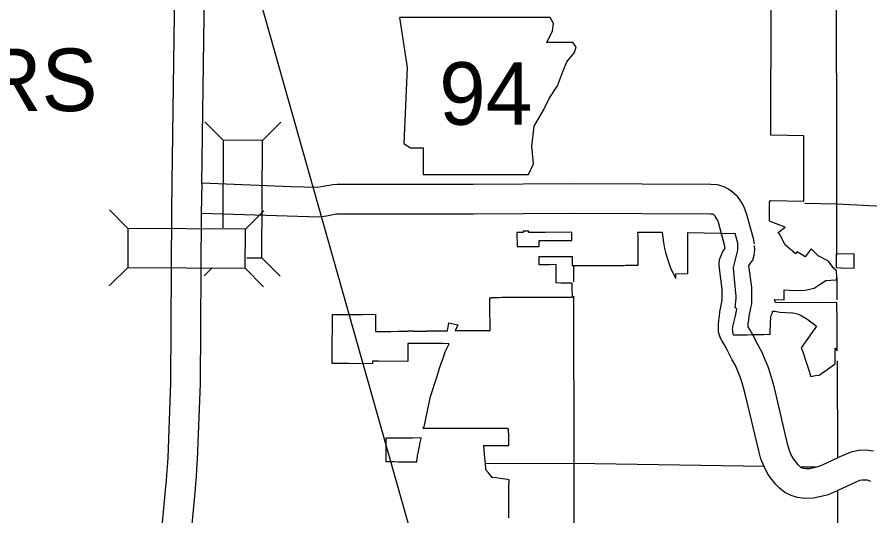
# Model space of a CAD drawing. Extents: x 309389.3 to 309420.2, y 336441.4 to 336461.2.
# Drawn here: x 309392.47 to 309393.778, y 336456.121 to 336456.886 of the extents above; entities that cross this region are included whole.
import ezdxf

# ---------------------------------------------------------------- set-up
doc = ezdxf.new("R2010")
doc.units = 0
for name, color, linetype in [('Level 24', 7, 'Continuous'), ('Level 37', 7, 'Continuous'), ('Level 4', 7, 'Continuous'), ('Level 62', 7, 'Continuous'), ('Level 63', 7, 'Continuous'), ('R_Axis Annot', 7, 'Continuous'), ('R_Contours', 7, 'Continuous')]:
    doc.layers.add(name, color=color, linetype=linetype)

msp = doc.modelspace()

# ---------------------------------------------------------------- linework, layer by layer
at = {"layer": 'Level 24'}
for points in [[(309392.8902, 336456.6257), (309392.7535, 336456.6309), (309392.7527, 336456.5848)], [(309393.6007, 336456.5379), (309393.5994, 336456.5464), (309393.5887, 336456.5845), (309393.5857, 336456.593), (309393.5825, 336456.5993), (309393.5789, 336456.6051), (309393.5747, 336456.6107), (309393.5673, 336456.6173), (309393.5608, 336456.6217), (309393.5544, 336456.6255), (309393.5439, 336456.6287), (309393.534, 336456.6289), (309393.3234, 336456.6302), (309393.1696, 336456.6292), (309392.9609, 336456.629), (309392.9541, 336456.6285), (309392.9489, 336456.6275), (309392.9444, 336456.6268), (309392.9364, 336456.6253), (309392.9308, 336456.6243), (309392.8902, 336456.6257)], [(309393.5558, 336456.531), (309393.5549, 336456.5367), (309393.5454, 336456.5706), (309393.5439, 336456.5749), (309393.5428, 336456.577), (309393.5412, 336456.5796), (309393.5411, 336456.5798), (309393.5394, 336456.5813), (309393.5364, 336456.5833), (309393.5363, 336456.5834), (309393.5335, 336456.5834), (309393.3234, 336456.5848), (309393.1698, 336456.5837), (309392.9626, 336456.5836), (309392.96, 336456.5834), (309392.957, 336456.5828), (309392.9522, 336456.582), (309392.9444, 336456.5806), (309392.934, 336456.5788), (309392.7527, 336456.5848)], [(309393.7832, 336456.22), (309393.7713, 336456.2213), (309393.7604, 336456.221), (309393.7488, 336456.2184), (309393.7371, 336456.214), (309393.7048, 336456.1987), (309393.6993, 336456.1965), (309393.692, 336456.1946), (309393.6854, 336456.193), (309393.6796, 336456.1929), (309393.6765, 336456.1933), (309393.674, 336456.1941), (309393.6719, 336456.1951), (309393.6697, 336456.197), (309393.6678, 336456.1988), (309393.6642, 336456.2035), (309393.66, 336456.2091), (309393.6567, 336456.2154), (309393.6538, 336456.2225), (309393.6521, 336456.2291), (309393.6313, 336456.3169), (309393.6284, 336456.328), (309393.6252, 336456.3383), (309393.6216, 336456.3495), (309393.6172, 336456.3601), (309393.6126, 336456.3711), (309393.6068, 336456.3817), (309393.5986, 336456.3976), (309393.5934, 336456.4065), (309393.5911, 336456.4109), (309393.591, 336456.4129), (309393.5912, 336456.4156), (309393.592, 336456.4205), (309393.5928, 336456.4269), (309393.5951, 336456.4401), (309393.5965, 336456.446), (309393.5969, 336456.4562), (309393.5965, 336456.4629), (309393.5965, 336456.4718), (309393.5923, 336456.5041), (309393.5923, 336456.5044), (309393.5923, 336456.5044), (309393.5938, 336456.5068), (309393.5981, 336456.513), (309393.6002, 336456.5209), (309393.6012, 336456.5289), (309393.6009, 336456.5353)], [(309393.7791, 336456.1736), (309393.7767, 336456.1744), (309393.7738, 336456.1753), (309393.7695, 336456.1757), (309393.766, 336456.1757), (309393.7618, 336456.1747), (309393.7549, 336456.1721), (309393.7229, 336456.157), (309393.7135, 336456.1532), (309393.703, 336456.1505), (309393.6912, 336456.1477), (309393.6773, 336456.1474), (309393.6668, 336456.1487), (309393.6569, 336456.1518), (309393.6471, 336456.1567), (309393.6393, 336456.163), (309393.6335, 336456.1687), (309393.628, 336456.1761), (309393.6215, 336456.1846), (309393.6154, 336456.1962), (309393.6106, 336456.2082), (309393.608, 336456.2182), (309393.5871, 336456.306), (309393.5847, 336456.3155), (309393.5818, 336456.3246), (309393.5789, 336456.334), (309393.5753, 336456.3426), (309393.5716, 336456.3513), (309393.5667, 336456.3603), (309393.5588, 336456.3756), (309393.5536, 336456.3845), (309393.5508, 336456.3899), (309393.5487, 336456.3935), (309393.5457, 336456.4023), (309393.5457, 336456.4089), (309393.5454, 336456.4138), (309393.5461, 336456.4211), (309393.547, 336456.4271), (309393.5479, 336456.4338), (309393.5506, 336456.4492), (309393.5513, 336456.4521), (309393.5514, 336456.4558), (309393.5511, 336456.4615), (309393.5511, 336456.4687), (309393.547, 336456.5001), (309393.5467, 336456.5058), (309393.5471, 336456.5138), (309393.5496, 336456.5202), (309393.5523, 336456.5262), (309393.5556, 336456.5314), (309393.5555, 336456.5335)]]:
    msp.add_lwpolyline(points, dxfattribs=at)
at = {"layer": 'Level 37'}
for p, q in [((309392.7864, 336456.697), (309392.7582, 336456.7254)), ((309392.8464, 336456.6966), (309392.8748, 336456.7247)), ((309392.7864, 336456.697), (309392.7856, 336456.5624)), ((309392.8464, 336456.6966), (309392.7864, 336456.697)), ((309392.8454, 336456.5166), (309392.8464, 336456.6966)), ((309392.6403, 336456.5617), (309392.6122, 336456.5902)), ((309392.8203, 336456.5607), (309392.8487, 336456.5889)), ((309392.8223, 336456.5168), (309392.8454, 336456.5166)), ((309392.8454, 336456.5166), (309392.8735, 336456.4882)), ((309392.64, 336456.5017), (309392.6115, 336456.4736)), ((309392.7692, 336456.501), (309392.7569, 336456.4888)), ((309392.82, 336456.5007), (309392.8481, 336456.4723))]:
    msp.add_line(p, q, dxfattribs=at)
msp.add_lwpolyline([(309392.64, 336456.5017), (309392.82, 336456.5007), (309392.8203, 336456.5607), (309392.6403, 336456.5617)], close=True, dxfattribs=at)
at = {"layer": 'Level 4'}
for points in [[(309393.7272, 336456.5204), (309393.7268, 336456.5996), (309393.7263, 336457.0003), (309393.7258, 336457.2014)], [(309393.6778, 336456.6003), (309393.7269, 336456.5994), (309394.129, 336456.579), (309394.5268, 336456.5747), (309394.8545, 336456.5709)], [(309393.3235, 336456.5053), (309393.3235, 336456.4797)], [(309393.7275, 336456.4523), (309393.7273, 336456.4858)], [(309393.3235, 336456.4578), (309393.3236, 336456.201), (309393.3228, 336455.7953), (309393.322, 336455.3953)], [(309393.7288, 336456.2097), (309393.728, 336456.3583)], [(309393.6155, 336456.1964), (309393.3236, 336456.2011), (309393.1883, 336456.2007)], [(309393.6938, 336456.1952), (309393.672, 336456.1955)], [(309393.7274, 336455.9452), (309393.7287, 336456.1596)]]:
    msp.add_lwpolyline(points, dxfattribs=at)
at = {"layer": 'Level 62'}
for points in [[(309393.6259, 336456.7821), (309393.6259, 336456.7825), (309393.626, 336456.8049), (309393.6261, 336456.8049), (309393.6261, 336456.8065), (309393.6262, 336456.8065), (309393.6263, 336456.8559), (309393.6263, 336456.8737), (309393.6263, 336456.9065)], [(309393.5707, 336456.4728), (309393.572, 336456.4578), (309393.5721, 336456.4549), (309393.5708, 336456.441), (309393.573, 336456.439), (309393.5728, 336456.439), (309393.5732, 336456.4378), (309393.571, 336456.4274), (309393.5675, 336456.4135), (309393.5672, 336456.4114), (309393.567, 336456.4099), (309393.567, 336456.4096), (309393.5669, 336456.4093), (309393.5668, 336456.4071), (309393.5669, 336456.405), (309393.5671, 336456.4029), (309393.5674, 336456.4007), (309393.5679, 336456.3983), (309393.5699, 336456.3983), (309393.5898, 336456.3985), (309393.5982, 336456.3987), (309393.6041, 336456.3988), (309393.6065, 336456.3989), (309393.6076, 336456.3989), (309393.6149, 336456.399), (309393.6232, 336456.3992), (309393.6245, 336456.3991), (309393.6246, 336456.3999), (309393.6247, 336456.4029), (309393.6254, 336456.4146), (309393.6261, 336456.427), (309393.6284, 336456.432), (309393.6284, 336456.4348), (309393.6326, 336456.4348), (309393.6344, 336456.4343), (309393.6397, 336456.4331), (309393.6594, 336456.4322), (309393.6669, 336456.4307), (309393.6726, 336456.4281), (309393.6774, 336456.425), (309393.6797, 336456.4238), (309393.6811, 336456.4228), (309393.6934, 336456.4137), (309393.6959, 336456.4118), (309393.6869, 336456.3989), (309393.685, 336456.3962), (309393.6725, 336456.3783), (309393.6747, 336456.3721), (309393.6801, 336456.3564), (309393.6832, 336456.3473), (309393.6872, 336456.3347), (309393.6944, 336456.3359), (309393.6998, 336456.3368), (309393.7243, 336456.3538), (309393.7243, 336456.3729), (309393.7243, 336456.3748), (309393.7243, 336456.3778), (309393.7277, 336456.3739), (309393.7275, 336456.3964), (309393.7275, 336456.399), (309393.7273, 336456.4177), (309393.7271, 336456.4479), (309393.7031, 336456.4476), (309393.6329, 336456.448), (309393.6315, 336456.4527), (309393.6464, 336456.4523), (309393.6464, 336456.4636), (309393.6464, 336456.4675), (309393.6623, 336456.4666), (309393.6787, 336456.467), (309393.6922, 336456.47), (309393.6998, 336456.475), (309393.7101, 336456.4818), (309393.7251, 336456.4828), (309393.7265, 336456.483), (309393.7268, 336456.483), (309393.7268, 336456.4867), (309393.7267, 336456.4965), (309393.7223, 336456.5002), (309393.7141, 336456.5115), (309393.6982, 336456.5195), (309393.6876, 336456.5305), (309393.6784, 336456.518), (309393.666, 336456.5258), (309393.6638, 336456.5227), (309393.6477, 336456.5363), (309393.6394, 336456.5521), (309393.6373, 336456.5553), (309393.648, 336456.5637), (309393.633, 336456.5693), (309393.6238, 336456.573), (309393.6239, 336456.575), (309393.6238, 336456.5841), (309393.6237, 336456.6021), (309393.6255, 336456.6047), (309393.6257, 336456.6047), (309393.6763, 336456.6035), (309393.6764, 336456.7037), (309393.6259, 336456.7048), (309393.6259, 336456.7821)], [(309393.195, 336456.4554), (309393.1974, 336456.4554), (309393.1974, 336456.4557), (309393.2094, 336456.4559), (309393.2132, 336456.456), (309393.2192, 336456.456), (309393.2217, 336456.456), (309393.2238, 336456.456), (309393.2256, 336456.456), (309393.232, 336456.456), (309393.2384, 336456.456), (309393.2448, 336456.456), (309393.2466, 336456.456), (309393.2512, 336456.456), (309393.2576, 336456.4561), (309393.264, 336456.4561), (309393.2704, 336456.4561), (309393.2715, 336456.4561), (309393.2768, 336456.4561), (309393.2833, 336456.4561), (309393.2897, 336456.4561), (309393.2964, 336456.4561), (309393.3034, 336456.4562), (309393.3105, 336456.4562), (309393.3169, 336456.4562), (309393.3216, 336456.4561), (309393.3216, 336456.4579), (309393.3215, 336456.4691), (309393.3214, 336456.4779), (309393.3194, 336456.4779), (309393.311, 336456.4778), (309393.3038, 336456.4777), (309393.2966, 336456.478), (309393.2966, 336456.4859), (309393.2966, 336456.4938), (309393.2967, 336456.5061), (309393.287, 336456.506), (309393.2807, 336456.506), (309393.2742, 336456.506), (309393.2706, 336456.506), (309393.2706, 336456.5185), (309393.3211, 336456.5185), (309393.3212, 336456.5061), (309393.3212, 336456.5049), (309393.323, 336456.5049), (309393.3314, 336456.5048), (309393.3367, 336456.5048), (309393.342, 336456.5048), (309393.3474, 336456.5048), (309393.3527, 336456.5048), (309393.3562, 336456.5048), (309393.357, 336456.5048), (309393.358, 336456.5048), (309393.3633, 336456.5048), (309393.3686, 336456.5048), (309393.3728, 336456.5049), (309393.3739, 336456.5049), (309393.3793, 336456.505), (309393.3846, 336456.505), (309393.386, 336456.5049), (309393.3899, 336456.505), (309393.3952, 336456.505), (309393.4005, 336456.505), (309393.4032, 336456.5051), (309393.4059, 336456.5051), (309393.4178, 336456.5052), (309393.4226, 336456.5052), (309393.4225, 336456.5139), (309393.4226, 336456.5202), (309393.4224, 336456.5256), (309393.4224, 336456.5309), (309393.4224, 336456.5362), (309393.4223, 336456.5429), (309393.4223, 336456.5496), (309393.4222, 336456.556), (309393.459, 336456.5561), (309393.4614, 336456.5402), (309393.4627, 336456.5308), (309393.4642, 336456.5247), (309393.4685, 336456.5114), (309393.4712, 336456.5041), (309393.4731, 336456.4984), (309393.48, 336456.4848), (309393.4801, 336456.4922), (309393.4988, 336456.4927), (309393.4987, 336456.5038), (309393.4988, 336456.5129), (309393.4987, 336456.542), (309393.4987, 336456.5553), (309393.5237, 336456.5549), (309393.5711, 336456.554), (309393.5714, 336456.5526), (309393.575, 336456.5397), (309393.5749, 336456.537), (309393.5745, 336456.5282), (309393.5722, 336456.5181), (309393.5681, 336456.5016), (309393.5686, 336456.5016), (309393.5682, 336456.5014), (309393.5707, 336456.4728)], [(309393.1296, 336456.2548), (309393.1285, 336456.2548), (309393.1278, 336456.2548), (309393.1256, 336456.2548), (309393.1239, 336456.2548), (309393.1218, 336456.2548), (309393.1202, 336456.2548), (309393.1179, 336456.2548), (309393.1164, 336456.2548), (309393.1142, 336456.2548), (309393.1126, 336456.2548), (309393.1105, 336456.2548), (309393.1088, 336456.2548), (309393.1066, 336456.2548), (309393.105, 336456.2548), (309393.1029, 336456.2548), (309393.1012, 336456.2548), (309393.0977, 336456.2548), (309393.0964, 336456.2548), (309393.0949, 336456.2548), (309393.0929, 336456.2549), (309393.0935, 336456.2571), (309393.0944, 336456.2571), (309393.1041, 336456.3038), (309393.1144, 336456.3352), (309393.1179, 336456.3474), (309393.1224, 336456.3599), (309393.1234, 336456.3627), (309393.1267, 336456.3721), (309393.1328, 336456.3848), (309393.1232, 336456.3849), (309393.1213, 336456.3849), (309393.1106, 336456.385), (309393.0996, 336456.3851), (309393.0691, 336456.3853), (309393.0693, 336456.3577), (309393.0242, 336456.3578), (309393.0191, 336456.3578), (309393.0151, 336456.3578), (309393.0151, 336456.3539), (309392.9782, 336456.3543), (309392.9534, 336456.3544), (309392.9534, 336456.3619), (309392.9535, 336456.3844), (309392.9535, 336456.3882), (309392.9535, 336456.3919), (309392.9536, 336456.4039), (309392.9539, 336456.4295), (309392.9991, 336456.4296), (309393.0196, 336456.4301), (309393.0196, 336456.4276), (309393.0198, 336456.4228), (309393.0198, 336456.4183), (309393.0199, 336456.412), (309393.02, 336456.4034), (309393.0284, 336456.4034), (309393.0312, 336456.4035), (309393.0433, 336456.4035), (309393.0543, 336456.4039), (309393.0691, 336456.4039), (309393.0691, 336456.4045), (309393.0782, 336456.4047), (309393.0782, 336456.404), (309393.0847, 336456.404), (309393.0893, 336456.4039), (309393.094, 336456.4039), (309393.0986, 336456.4039), (309393.0986, 336456.4044), (309393.0993, 336456.4044), (309393.1032, 336456.4044), (309393.1078, 336456.4044), (309393.1119, 336456.4044), (309393.113, 336456.4044), (309393.1176, 336456.4044), (309393.1211, 336456.4044), (309393.1222, 336456.4044), (309393.1268, 336456.4044), (309393.1301, 336456.4044), (309393.1323, 336456.4167), (309393.1324, 336456.4169), (309393.146, 336456.4139), (309393.142, 336456.4046), (309393.145, 336456.4049), (309393.1538, 336456.405), (309393.1599, 336456.405), (309393.1659, 336456.405), (309393.1719, 336456.405), (309393.178, 336456.405), (309393.184, 336456.405), (309393.1889, 336456.405), (309393.1955, 336456.405), (309393.1955, 336456.4159), (309393.1954, 336456.4219), (309393.1953, 336456.428), (309393.1952, 336456.434), (309393.1952, 336456.44), (309393.1951, 336456.446), (309393.195, 336456.4532), (309393.195, 336456.4536), (309393.195, 336456.4554)], [(309393.2244, 336456.1178), (309393.2244, 336456.1223), (309393.2244, 336456.1286), (309393.2244, 336456.1335), (309393.2244, 336456.1384), (309393.2244, 336456.143), (309393.2244, 336456.1483), (309393.2244, 336456.1532), (309393.2244, 336456.1581), (309393.2244, 336456.163), (309393.2245, 336456.1762), (309393.2225, 336456.1765), (309393.2102, 336456.1781), (309393.2047, 336456.1789), (309393.1995, 336456.1795), (309393.1987, 336456.1796), (309393.1955, 336456.1835), (309393.1931, 336456.1865), (309393.1891, 336456.1913), (309393.1882, 336456.2023), (309393.188, 336456.2045), (309393.1871, 336456.2154), (309393.186, 336456.2289), (309393.1965, 336456.2288), (309393.2242, 336456.2286), (309393.2242, 336456.2299), (309393.224, 336456.2414), (309393.2239, 336456.2541), (309393.2221, 336456.2541), (309393.2221, 336456.2549), (309393.2027, 336456.2549), (309393.1964, 336456.2549), (309393.1945, 336456.2549), (309393.1842, 336456.2549), (309393.1766, 336456.2549), (309393.1749, 336456.2549), (309393.1714, 336456.2549), (309393.1697, 336456.2549), (309393.167, 336456.2549), (309393.1654, 336456.2549), (309393.1631, 336456.2549), (309393.1615, 336456.2549), (309393.1593, 336456.2549), (309393.1576, 336456.2549), (309393.1555, 336456.2548), (309393.1539, 336456.2548), (309393.15, 336456.2548), (309393.1484, 336456.2548), (309393.1469, 336456.2548), (309393.1462, 336456.2548), (309393.1446, 336456.2548), (309393.1409, 336456.2548), (309393.1391, 336456.2548), (309393.137, 336456.2548), (309393.1353, 336456.2548), (309393.1332, 336456.2548), (309393.1315, 336456.2548), (309393.1296, 336456.2548)]]:
    msp.add_lwpolyline(points, dxfattribs=at)
for points in [[(309393.2707, 336456.5337), (309393.2707, 336456.5434), (309393.3209, 336456.5434), (309393.3208, 336456.5558), (309393.28, 336456.5552), (309393.2759, 336456.5553), (309393.2708, 336456.5553), (309393.2677, 336456.5553), (309393.255, 336456.5554), (309393.255, 336456.5573), (309393.2462, 336456.5573), (309393.2462, 336456.5554), (309393.2457, 336456.5554), (309393.2364, 336456.5555), (309393.2367, 336456.5337), (309393.2449, 336456.5337), (309393.2487, 336456.5337), (309393.2525, 336456.5337), (309393.2563, 336456.5337), (309393.2671, 336456.5337)], [(309393.7531, 336456.5002), (309393.7333, 336456.5008), (309393.7266, 336456.5011), (309393.7264, 336456.5232), (309393.753, 336456.5229)], [(309393.0832, 336456.2038), (309393.0833, 336456.2048), (309393.0836, 336456.2084), (309393.084, 336456.212), (309393.0841, 336456.2129), (309393.0856, 336456.2202), (309393.0875, 336456.2295), (309393.0878, 336456.231), (309393.0896, 336456.2393), (309393.0898, 336456.2404), (309393.0763, 336456.2399), (309393.0356, 336456.2401), (309393.0356, 336456.2365), (309393.0356, 336456.2319), (309393.0356, 336456.2317), (309393.0356, 336456.2274), (309393.0356, 336456.2228), (309393.0356, 336456.2195), (309393.0356, 336456.2183), (309393.0356, 336456.2096), (309393.0356, 336456.2094), (309393.0356, 336456.2039), (309393.0361, 336456.2039), (309393.0421, 336456.2039), (309393.0482, 336456.2039), (309393.0543, 336456.2038), (309393.0605, 336456.2038), (309393.0667, 336456.2038), (309393.0784, 336456.2038), (309393.0801, 336456.2038)]]:
    msp.add_lwpolyline(points, close=True, dxfattribs=at)
at = {"layer": 'Level 63'}
msp.add_line((309393.4111, 336454.9055), (309392.7786, 336457.1397), dxfattribs=at)
at = {"layer": 'R_Axis Annot'}
for points in [[(309392.7077, 336456.5873), (309392.7081, 336456.6325), (309392.7125, 336456.9642), (309392.7157, 336456.9888), (309392.7154, 336456.9973), (309392.7159, 336457.0121), (309392.7176, 336457.1549), (309392.7174, 336457.19)], [(309392.7536, 336456.6308), (309392.7579, 336456.9609), (309392.7613, 336456.9867), (309392.7609, 336456.9973), (309392.7614, 336457.011), (309392.763, 336457.1548), (309392.7629, 336457.1904)], [(309392.6838, 336456.0102), (309392.6983, 336456.1659), (309392.6991, 336456.1743), (309392.6998, 336456.1835), (309392.7008, 336456.1957), (309392.7017, 336456.2097), (309392.7062, 336456.3248), (309392.7077, 336456.5873)], [(309392.729, 336456.006), (309392.7436, 336456.1615), (309392.7444, 336456.1704), (309392.7451, 336456.18), (309392.7461, 336456.1924), (309392.7471, 336456.2072), (309392.7517, 336456.3238), (309392.7532, 336456.5846)]]:
    msp.add_lwpolyline(points, dxfattribs=at)
at = {"layer": 'R_Contours'}
msp.add_lwpolyline([(309393.0568, 336456.8853), (309393.0683, 336456.8084), (309393.0632, 336456.6917), (309393.0735, 336456.6853), (309393.0927, 336456.6853), (309393.0927, 336456.6443), (309393.2542, 336456.6443), (309393.2619, 336456.661), (309393.2593, 336456.6879), (309393.2631, 336456.7187), (309393.2772, 336456.743), (309393.2862, 336456.761), (309393.299, 336456.7802), (309393.3067, 336456.8007), (309393.3131, 336456.8173), (309393.3247, 336456.8314), (309393.3272, 336456.8404), (309393.3221, 336456.8468), (309393.2824, 336456.8468), (309393.2913, 336456.8648), (309393.2926, 336456.8763), (309393.2873, 336456.8852)], close=True, dxfattribs=at)

# ---------------------------------------------------------------- texts
at = {"layer": 'Level 62'}
msp.add_text('ROGERS', height=0.096, dxfattribs=at).set_placement((309392.0371, 336456.7416))
at = {"layer": 'R_Contours'}
msp.add_text('94', height=0.096, dxfattribs=at).set_placement((309393.1174, 336456.7207))

doc.saveas('drawing.dxf')
